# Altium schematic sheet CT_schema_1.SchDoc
size 456 x 210 mm
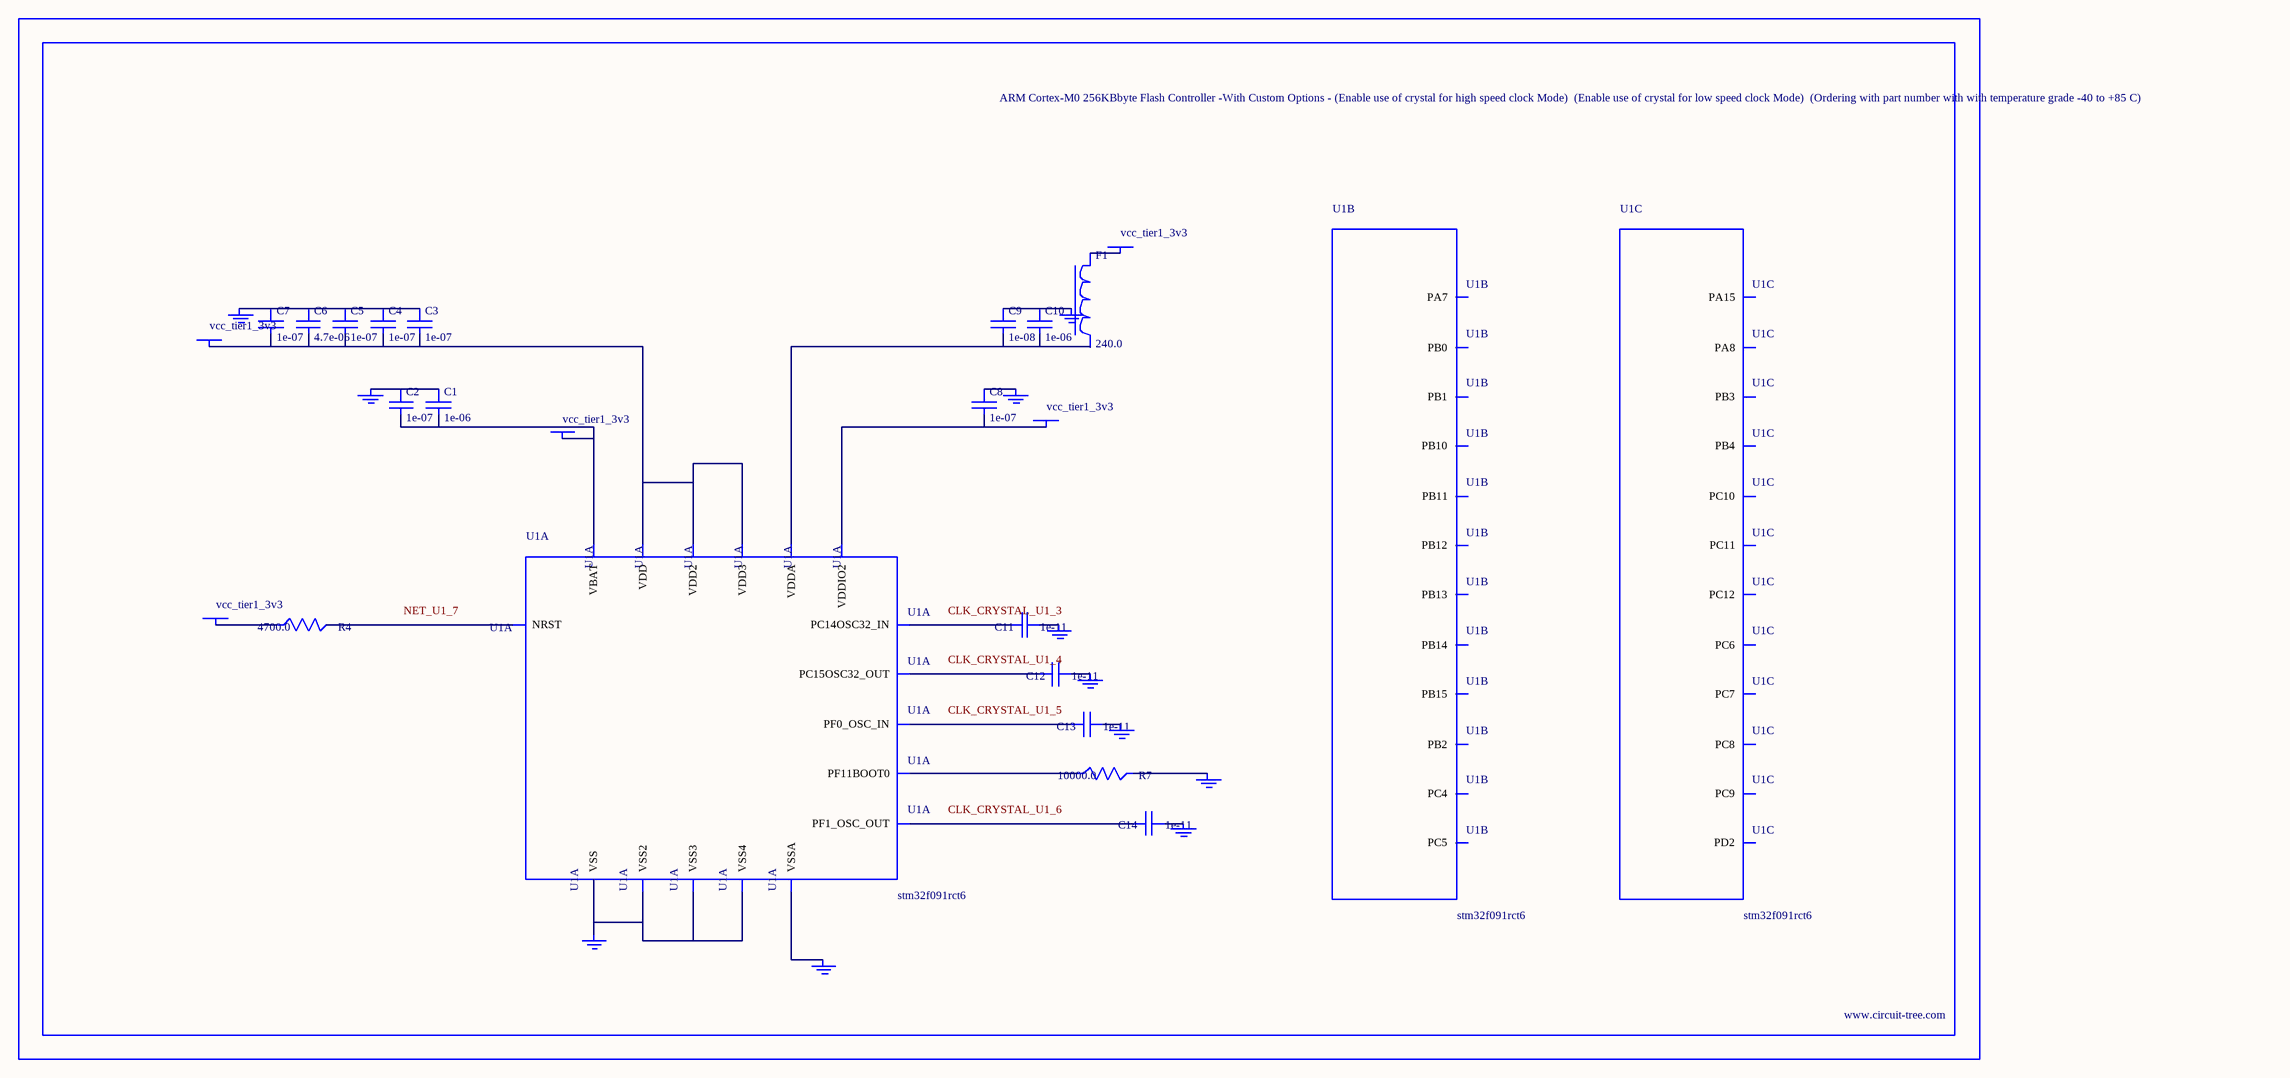
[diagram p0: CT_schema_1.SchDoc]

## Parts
BORDER0  (no value)
C1  1e-06  [C0603]
C2  1e-07  [C0603]
C3  1e-07  [C0603]
C4  1e-07  [C0603]
C5  1e-07  [C0603]
C6  4.7e-06  [C0603]
C7  1e-07  [C0603]
C8  1e-07  [C0603]
C9  1e-08  [C0603]
C10  1e-06  [C0603]
C11  1e-11  [C0402]
C12  1e-11  [C0402]
C13  1e-11  [C0402]
C14  1e-11  [C0402]
F1  240.0  [L0603]
GND_INSTANCE_0_0  (no value)
GND_INSTANCE_0_1  (no value)
GND_INSTANCE_0_2  (no value)
GND_INSTANCE_0_3  (no value)
GND_INSTANCE_0_4  (no value)
GND_INSTANCE_0_5  (no value)
GND_INSTANCE_0_6  (no value)
GND_INSTANCE_0_7  (no value)
GND_INSTANCE_0_8  (no value)
GND_INSTANCE_0_9  (no value)
GND_INSTANCE_0_10  (no value)
POWER_INSTANCE_0_0  vcc_tier1_3v3
POWER_INSTANCE_0_1  vcc_tier1_3v3
POWER_INSTANCE_0_2  vcc_tier1_3v3
POWER_INSTANCE_0_3  vcc_tier1_3v3
POWER_INSTANCE_0_4  vcc_tier1_3v3
R4  4700.0  [R0603]
R7  10000.0  [R0603]
U1  stm32f091rct6  [LQFP64]  (parts A,B,C of 7)

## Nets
NetC1_1: C1.1 C2.1 GND_INSTANCE_0_0.0(GND)
NetC1_2: C1.2 C2.2 POWER_INSTANCE_0_0.0(PWR) U1.1(VBAT)
NetC3_1: C3.1 C4.1 C5.1 C6.1 C7.1 GND_INSTANCE_0_7.0(GND)
NetC3_2: C3.2 C4.2 C5.2 C6.2 C7.2 POWER_INSTANCE_0_2.0(PWR) U1.19(VDD) U1.32(VDD2) U1.64(VDD3)
NetC8_1: C8.1 GND_INSTANCE_0_8.0(GND)
NetC8_2: C8.2 POWER_INSTANCE_0_3.0(PWR) U1.48(VDDIO2)
NetC9_1: C9.1 C10.1 GND_INSTANCE_0_6.0(GND)
NetC9_2: C9.2 C10.2 U1.13(VDDA)
NetC11_1: C11.1 GND_INSTANCE_0_1.0(GND)
NetC11_2: C11.2 U1.3(PC14OSC32_IN)
NetC12_1: C12.1 GND_INSTANCE_0_2.0(GND)
NetC12_2: C12.2 U1.4(PC15OSC32_OUT)
NetC13_1: C13.1 GND_INSTANCE_0_3.0(GND)
NetC13_2: C13.2 U1.5(PF0_OSC_IN)
NetC14_1: C14.1 GND_INSTANCE_0_4.0(GND)
NetC14_2: C14.2 U1.6(PF1_OSC_OUT)
NetF1_1: F1.1 POWER_INSTANCE_0_1.0(PWR)
NetGND_INSTANCE_0_5_0: GND_INSTANCE_0_5.0(GND) U1.12(VSSA)
NetGND_INSTANCE_0_9_0: GND_INSTANCE_0_9.0(GND) R7.2
NetGND_INSTANCE_0_10_0: GND_INSTANCE_0_10.0(GND) U1.18(VSS) U1.31(VSS2) U1.47(VSS3) U1.63(VSS4)
NetPOWER_INSTANCE_0_4_0: POWER_INSTANCE_0_4.0(PWR) R4.1
NetR4_2: R4.2 U1.7(NRST)
NetR7_1: R7.1 U1.60(PF11BOOT0)

Not connected (* = marked no-connect by the designer): F1 2; U1 23(PA7) 24(PC4) 25(PC5) 26(PB0) 27(PB1) 28(PB2) 29(PB10) 30(PB11) 33(PB12) 34(PB13) 35(PB14) 36(PB15) 37(PC6) 38(PC7) 39(PC8) 40(PC9) 41(PA8) 50(PA15) 51(PC10) 52(PC11) 53(PC12) 54(PD2) 55(PB3) 56(PB4)

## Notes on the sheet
- Labels drawn without touching a wire or pin: CLK_CRYSTAL_U1_3, CLK_CRYSTAL_U1_4, CLK_CRYSTAL_U1_5, CLK_CRYSTAL_U1_6, NET_U1_7

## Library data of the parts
BORDER0 = BORDER_PAGE0
C1 C10 = C0603C105K3RACTU
C2-C5 C7 C8 = 06035C104K4Z2A
C6 = GRM188R6YA475KE15D
C9 = 06035C103K4Z2A
C11-C14 = C0402C100K3GACTU
F1 = Z0603C241ASMST
GND_INSTANCE_0_0-GND_INSTANCE_0_10 = GND
POWER_INSTANCE_0_0-POWER_INSTANCE_0_4 = PWR
R4 = RC0603JR-074K7L
R7 = RC0603JR-0710KL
